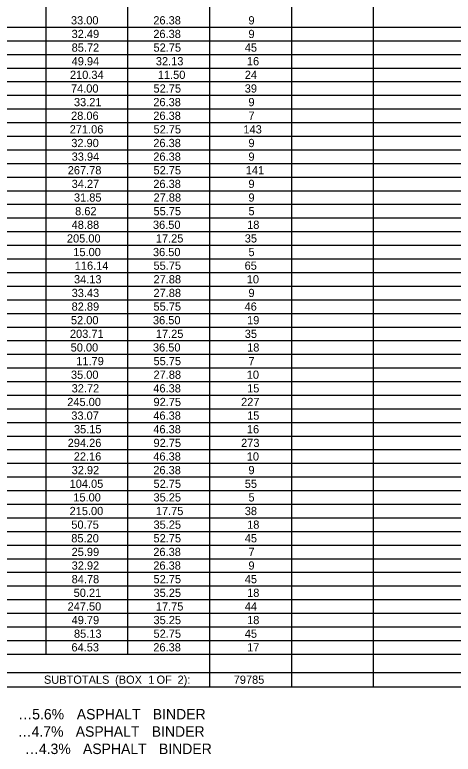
# Model space of a CAD drawing. Extents: x 1226590 to 1228573, y 151304 to 154224.
# Drawn here: x 1226844.3 to 1227053.8, y 151452.7 to 151806.5 of the extents above; entities that cross this region are included whole.
import ezdxf

# ---------------------------------------------------------------- set-up
doc = ezdxf.new("R2010")
doc.units = 0
doc.layers.add('R_Dimension', color=7, linetype='Continuous')

msp = doc.modelspace()

# ---------------------------------------------------------------- linework, layer by layer
at = {"layer": 'R_Dimension'}
for p, q in [((1226859.24, 151500.6), (1226859.24, 151957.19)), ((1226898.37, 151500.6), (1226898.37, 151957.19)), ((1226937.51, 151484.92), (1226937.51, 151957.19)), ((1226976.64, 151484.92), (1226976.64, 151957.19)), ((1227015.78, 151484.92), (1227015.78, 151957.19)), ((1226590.27, 151800.64), (1228150.73, 151800.64)), ((1226590.27, 151794.12), (1228150.73, 151794.12)), ((1226590.27, 151787.6), (1228150.73, 151787.6)), ((1226590.27, 151781.08), (1228150.73, 151781.08)), ((1226590.27, 151774.55), (1228150.73, 151774.55)), ((1226590.27, 151768.03), (1228150.73, 151768.03)), ((1226590.27, 151761.51), (1228150.73, 151761.51)), ((1226590.27, 151754.99), (1228150.73, 151754.99)), ((1226590.27, 151748.46), (1228150.73, 151748.46)), ((1226590.27, 151741.94), (1228150.73, 151741.94)), ((1226590.27, 151735.42), (1228150.73, 151735.42)), ((1226590.27, 151728.89), (1228150.73, 151728.89)), ((1226590.27, 151722.37), (1228150.73, 151722.37)), ((1226590.27, 151715.85), (1228150.73, 151715.85)), ((1226590.27, 151709.33), (1228150.73, 151709.33)), ((1226590.27, 151702.8), (1228150.73, 151702.8)), ((1226590.27, 151696.28), (1228150.73, 151696.28)), ((1226590.27, 151689.76), (1228150.73, 151689.76)), ((1226590.27, 151683.24), (1228150.73, 151683.24)), ((1226590.27, 151676.71), (1228150.73, 151676.71)), ((1226590.27, 151670.19), (1228150.73, 151670.19)), ((1226590.27, 151663.67), (1228150.73, 151663.67)), ((1226590.27, 151657.14), (1228150.73, 151657.14)), ((1226590.27, 151650.62), (1228150.73, 151650.62)), ((1226590.27, 151644.1), (1228150.73, 151644.1)), ((1226590.27, 151637.58), (1228150.73, 151637.58)), ((1226590.27, 151631.05), (1228150.73, 151631.05)), ((1226590.27, 151624.53), (1228150.73, 151624.53)), ((1226590.27, 151618.01), (1228150.73, 151618.01)), ((1226590.27, 151611.49), (1228150.73, 151611.49)), ((1226590.27, 151604.96), (1228150.73, 151604.96)), ((1226590.27, 151598.44), (1228150.73, 151598.44)), ((1226590.27, 151591.92), (1228150.73, 151591.92)), ((1226590.27, 151585.4), (1228150.73, 151585.4)), ((1226590.27, 151578.87), (1228150.73, 151578.87)), ((1226590.27, 151572.35), (1228150.73, 151572.35)), ((1226590.27, 151565.83), (1228150.73, 151565.83)), ((1226590.27, 151559.3), (1228150.73, 151559.3)), ((1226590.27, 151552.78), (1228150.73, 151552.78)), ((1226590.27, 151546.26), (1228150.73, 151546.26)), ((1226590.27, 151539.74), (1228150.73, 151539.74)), ((1226590.27, 151533.21), (1228150.73, 151533.21)), ((1226590.27, 151526.69), (1228150.73, 151526.69)), ((1226590.27, 151520.17), (1228150.73, 151520.17)), ((1226590.27, 151513.65), (1228150.73, 151513.65)), ((1226590.27, 151507.12), (1228150.73, 151507.12)), ((1226590.27, 151500.6), (1228150.73, 151500.6)), ((1226590.27, 151491.83), (1228150.75, 151491.83)), ((1226590.27, 151484.92), (1228150.75, 151484.92))]:
    msp.add_line(p, q, dxfattribs=at)

# ---------------------------------------------------------------- texts
for s, height, p in [('33.00', 3.935, (1226871.1, 151801.94)), ('26.38', 3.935, (1226910.47, 151801.94)), ('9', 3.94, (1226955.94, 151801.94)), ('32.49', 3.935, (1226871.41, 151795.42)), ('26.38', 3.935, (1226910.47, 151795.42)), ('9', 3.94, (1226955.94, 151795.42)), ('85.72', 3.935, (1226871.43, 151788.89)), ('52.75', 3.935, (1226910.56, 151788.89)), ('45', 3.935, (1226954.19, 151788.89)), ('49.94', 3.935, (1226871.43, 151782.37)), ('32.13', 3.935, (1226911.68, 151782.37)), ('16', 3.935, (1226955.2, 151782.37)), ('210.34', 3.935, (1226870.62, 151775.85)), ('11.50', 3.935, (1226912.63, 151775.85)), ('24', 3.935, (1226954.19, 151775.85)), ('74.00', 3.935, (1226871.1, 151769.32)), ('52.75', 3.935, (1226910.56, 151769.32)), ('39', 3.935, (1226954.18, 151769.32)), ('33.21', 3.935, (1226872.54, 151762.8)), ('26.38', 3.935, (1226910.47, 151762.8)), ('9', 3.94, (1226955.94, 151762.8)), ('28.06', 3.935, (1226871.17, 151756.28)), ('26.38', 3.935, (1226910.47, 151756.28)), ('7', 3.94, (1226955.96, 151756.28)), ('271.06', 3.935, (1226870.51, 151749.76)), ('52.75', 3.935, (1226910.56, 151749.76)), ('143', 3.935, (1226953.54, 151749.76)), ('32.90', 3.935, (1226871.26, 151743.23)), ('26.38', 3.935, (1226910.47, 151743.23)), ('9', 3.94, (1226955.94, 151743.23)), ('33.94', 3.935, (1226871.43, 151736.71)), ('26.38', 3.935, (1226910.47, 151736.71)), ('9', 3.94, (1226955.94, 151736.71)), ('267.78', 3.935, (1226869.57, 151730.19)), ('52.75', 3.935, (1226910.56, 151730.19)), ('141', 3.935, (1226954.66, 151730.19)), ('34.27', 3.935, (1226871.43, 151723.67)), ('26.38', 3.935, (1226910.47, 151723.67)), ('9', 3.94, (1226955.94, 151723.67)), ('31.85', 3.935, (1226872.54, 151717.14)), ('27.88', 3.935, (1226910.56, 151717.14)), ('9', 3.94, (1226955.94, 151717.14)), ('8.62', 3.935, (1226873.1, 151710.62)), ('55.75', 3.935, (1226910.56, 151710.62)), ('5', 3.94, (1226955.96, 151710.62)), ('48.88', 3.935, (1226871.43, 151704.1)), ('36.50', 3.935, (1226910.3, 151704.1)), ('18', 3.935, (1226955.31, 151704.1)), ('205.00', 3.935, (1226869.18, 151697.57)), ('17.25', 3.935, (1226911.68, 151697.57)), ('35', 3.935, (1226954.19, 151697.57)), ('15.00', 3.935, (1226872.22, 151691.05)), ('36.50', 3.935, (1226910.3, 151691.05)), ('5', 3.94, (1226955.96, 151691.05)), ('116.14', 3.935, (1226872.92, 151684.53)), ('55.75', 3.935, (1226910.56, 151684.53)), ('65', 3.935, (1226954.1, 151684.53)), ('34.13', 3.935, (1226872.54, 151678.01)), ('27.88', 3.935, (1226910.56, 151678.01)), ('10', 3.935, (1226955.14, 151678.01)), ('33.43', 3.935, (1226871.43, 151671.48)), ('27.88', 3.935, (1226910.56, 151671.48)), ('9', 3.94, (1226955.94, 151671.48)), ('82.89', 3.935, (1226871.41, 151664.96)), ('55.75', 3.935, (1226910.56, 151664.96)), ('46', 3.935, (1226954.09, 151664.96)), ('52.00', 3.935, (1226871.1, 151658.44)), ('36.50', 3.935, (1226910.3, 151658.44)), ('19', 3.935, (1226955.29, 151658.44)), ('203.71', 3.935, (1226870.62, 151651.92)), ('17.25', 3.935, (1226911.68, 151651.92)), ('35', 3.935, (1226954.19, 151651.92)), ('50.00', 3.935, (1226870.95, 151645.39)), ('36.50', 3.935, (1226910.3, 151645.39)), ('18', 3.935, (1226955.31, 151645.39)), ('11.79', 3.935, (1226873.64, 151638.87)), ('55.75', 3.935, (1226910.56, 151638.87)), ('7', 3.94, (1226955.96, 151638.87)), ('35.00', 3.935, (1226871.1, 151632.35)), ('27.88', 3.935, (1226910.56, 151632.35)), ('10', 3.935, (1226955.14, 151632.35)), ('32.72', 3.935, (1226871.43, 151625.83)), ('46.38', 3.935, (1226910.47, 151625.83)), ('15', 3.935, (1226955.31, 151625.83)), ('245.00', 3.935, (1226869.34, 151619.3)), ('92.75', 3.935, (1226910.56, 151619.3)), ('227', 3.935, (1226952.43, 151619.3)), ('33.07', 3.935, (1226871.27, 151612.78)), ('46.38', 3.935, (1226910.47, 151612.78)), ('15', 3.935, (1226955.31, 151612.78)), ('35.15', 3.935, (1226872.54, 151606.26)), ('46.38', 3.935, (1226910.47, 151606.26)), ('16', 3.935, (1226955.2, 151606.26)), ('294.26', 3.935, (1226869.55, 151599.73)), ('92.75', 3.935, (1226910.56, 151599.73)), ('273', 3.935, (1226952.43, 151599.73)), ('22.16', 3.935, (1226872.44, 151593.21)), ('46.38', 3.935, (1226910.47, 151593.21)), ('10', 3.935, (1226955.14, 151593.21)), ('32.92', 3.935, (1226871.43, 151586.69)), ('26.38', 3.935, (1226910.47, 151586.69)), ('9', 3.94, (1226955.94, 151586.69)), ('104.05', 3.935, (1226870.47, 151580.17)), ('52.75', 3.935, (1226910.56, 151580.17)), ('55', 3.935, (1226954.19, 151580.17)), ('15.00', 3.935, (1226872.22, 151573.64)), ('35.25', 3.935, (1226910.56, 151573.64)), ('5', 3.94, (1226955.96, 151573.64)), ('215.00', 3.935, (1226870.45, 151567.12)), ('17.75', 3.935, (1226911.68, 151567.12)), ('38', 3.935, (1226954.19, 151567.12)), ('50.75', 3.935, (1226871.27, 151560.6)), ('35.25', 3.935, (1226910.56, 151560.6)), ('18', 3.935, (1226955.31, 151560.6)), ('85.20', 3.935, (1226871.26, 151554.08)), ('52.75', 3.935, (1226910.56, 151554.08)), ('45', 3.935, (1226954.19, 151554.08)), ('25.99', 3.935, (1226871.41, 151547.55)), ('26.38', 3.935, (1226910.47, 151547.55)), ('7', 3.94, (1226955.96, 151547.55)), ('32.92', 3.935, (1226871.43, 151541.03)), ('26.38', 3.935, (1226910.47, 151541.03)), ('9', 3.94, (1226955.94, 151541.03)), ('84.78', 3.935, (1226871.43, 151534.51)), ('52.75', 3.935, (1226910.56, 151534.51)), ('45', 3.935, (1226954.19, 151534.51)), ('50.21', 3.935, (1226872.39, 151527.98)), ('35.25', 3.935, (1226910.56, 151527.98)), ('18', 3.935, (1226955.31, 151527.98)), ('247.50', 3.935, (1226869.49, 151521.46)), ('17.75', 3.935, (1226911.68, 151521.46)), ('44', 3.935, (1226954.19, 151521.46)), ('49.79', 3.935, (1226871.41, 151514.94)), ('35.25', 3.935, (1226910.56, 151514.94)), ('18', 3.935, (1226955.31, 151514.94)), ('85.13', 3.935, (1226872.54, 151508.42)), ('52.75', 3.935, (1226910.56, 151508.42)), ('45', 3.935, (1226954.19, 151508.42)), ('64.53', 3.935, (1226871.34, 151501.89)), ('26.38', 3.935, (1226910.47, 151501.89)), ('17', 3.935, (1226955.31, 151501.89)), ('SUBTOTALS', 3.935, (1226858.19, 151486.4)), (' (BOX', 3.935, (1226890.73, 151486.4)), (' 1', 3.935, (1226906.62, 151486.4)), (' OF', 3.935, (1226910.56, 151486.4)), (' 2):', 3.935, (1226920.6, 151486.4)), ('79785', 3.935, (1226948.9, 151486.4)), ('…5.6% ', 5, (1226845.89, 151469.34)), ('ASPHALT ', 5, (1226873.88, 151469.34)), ('BINDER', 5, (1226910.22, 151469.34)), ('ASPHALT ', 5, (1226873.37, 151461.06)), ('…4.7% ', 5, (1226845.62, 151461.06)), ('BINDER', 5, (1226909.71, 151461.06)), ('…4.3% ', 5, (1226849.08, 151452.77)), ('ASPHALT ', 5, (1226876.84, 151452.77)), ('BINDER', 5, (1226913.17, 151452.77))]:
    msp.add_text(s, height=height, dxfattribs=at).set_placement(p)

doc.saveas('drawing.dxf')
